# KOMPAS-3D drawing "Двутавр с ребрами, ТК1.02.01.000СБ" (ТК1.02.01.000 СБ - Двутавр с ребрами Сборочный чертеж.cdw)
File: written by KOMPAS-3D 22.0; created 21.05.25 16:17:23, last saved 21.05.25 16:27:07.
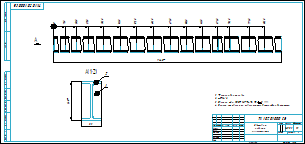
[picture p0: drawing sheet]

Sheet 1: A4x3, landscape

Document properties: Автор: TC; Масса: 149.81249; Форматы листов документа: A4@4~3

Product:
- Part/product: Двутавр с ребрами  | designation ТК1.02.01.000СБ
    Масса: 149.81249
    Форматы листов документа: A4@4~3
    source file: ТК1.02.01.000 - Двутавр с ребрами.spw
  - Component [standard]: Двутавр $d 16 ГОСТ 8239-89 ; Ст3сп ГОСТ 535-2005$  | qty 1  | pos. 2  | Масса: 146.411186; Раздел спецификации: Материалы; Рассекать на разрезах: no; additional columns: 16; VIEWPOINT:4c07c083-d9fb-fddf-3729-5b8bea8ed7b8
  - Component [detail]: Ребро жесткости  | designation ТК1.02.01.001  | qty 16  | pos. 1  | Материал: Сталь 09Г2С ГОСТ 19281-2014 (density 7850 kg/m3); Масса: 0.212581; Форматы листов документа: A4; source file: Ребро жесткости.cdw, Ребро жесткости.m3d, ТК1.02.01.001 - Ребро жесткости.cdw

Specification table, sheet 1 (Обозначение):
  а
Title block, sheet 2: Наименование: Двутавр с / ребрами / Сборочный чертеж; Масса: 149,81; sheet number: 1; Форматы листов документа: A4 3; stored path: D:\Рабочая папка\АРХИВ\612\05\Задание №6 - Тележка для крыши\3Д\Рама направляющих\ТК1.02.01.000 СБ - Двутавр с ребрами Сборочный чертеж.cdw
Specification table, sheet 2 (Обозначение):
  а

Views: Проекционный вид 3, Вид по стрелке А
Referenced files in D:\Рабочая папка\АРХИВ\612\05\Задание №6 - Тележка для крыши\3Д\Рама направляющих\: Двутавр с ребрами.a3d, Ребро жесткости.m3d, Ребро жесткости.cdw, ТК1.02.01.001 - Ребро жесткости.cdw
Referenced files in C:\Program Files\ASCON\KOMPAS-3D v22\Libs\PolynomLib\DATA\vault\Methods\Kompas\3D\: PLib_IBeams_GOST_8239_1501.m3d
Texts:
  ТК1.02.01.000
  Двутавр   16 ГОСТ 8239-89   Ст3сп ГОСТ 535-2005
  Двутавр
  ГОСТ
  Ст3сп
  BOSimple***PART:d1e4b814-fa26-d110-823d-d70c895bd231***SHORTLOC:B94B_A66A3A23F44E414C[16]
  VIEWPOINT:4c07c083-d9fb-fddf-3729-5b8bea8ed7b8
  ТК1.02.01.001
  Ребро жесткости
  BOSimple***Material:4ccf0190-16b6-4223-9222-aa108d28a442
  Двутавр $d 16 ГОСТ 8239-89 ; Ст3сп ГОСТ 535-2005$
  Двутавр  16 ГОСТ 8239-89 / Ст3сп ГОСТ 535-2005
  ТК1.02.01.001 Ребро жесткости
  Двутавр с ребрами
  ТК1.02.01.000
  ТК1.02.01.000 СБ Двутавр с ребрами
Dimensions and other numbers on the sheet: 9240; 718; 1318; 1918; 2518; 3118; 3718; 4318; 4918; 5518; 6118; 6718; 7318; 7918; 8518; 160; 2; 1; 81; 3; 4; 89; 2005; 16; 1:1; 149,81

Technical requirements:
  *Размеры для справок.
  ±IT14/2.
  Сварные швы: ГОСТ 14771-76 Т3- 5  .
  Брызги от сварки на поверхностях деталей не допустимы.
